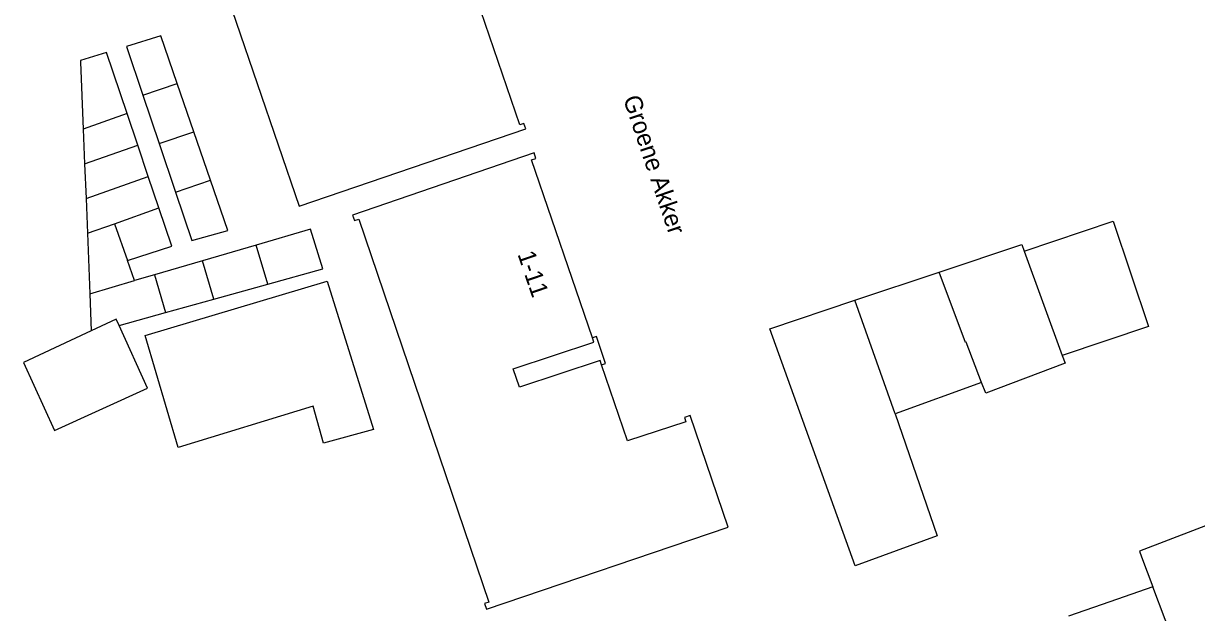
# Model space of a CAD drawing. Extents: x 159377 to 159983, y 382996 to 383595.
# Drawn here: x 159781.2 to 159847.9, y 383370 to 383403.5 of the extents above; entities that cross this region are included whole.
import ezdxf

# ---------------------------------------------------------------- set-up
doc = ezdxf.new("R2010")
doc.units = 0
for name, color, linetype in [('IMGEO_Openbare_ruimte_label', 7, 'Continuous'), ('IMGEO_Pand', 7, 'Continuous'), ('IMGEO_Pand_nummerreeks', 7, 'Continuous'), ('IMGEO_Voetpad_op_trap', 7, 'Continuous')]:
    doc.layers.add(name, color=color, linetype=linetype)

msp = doc.modelspace()

# ---------------------------------------------------------------- linework, layer by layer
at = {"layer": 'IMGEO_Pand'}
for points in [[(159802.443, 383426.11), (159787.292, 383421.008), (159796.842, 383393.077), (159809.724, 383397.481), (159809.618, 383397.783), (159809.378, 383397.699), (159805.931, 383407.814)], [(159789.909, 383400.061), (159788.98, 383402.759), (159787.012, 383402.158), (159787.944, 383399.398)], [(159787.05, 383398.343), (159785.875, 383401.81), (159784.411, 383401.363), (159784.414, 383401.275), (159784.564, 383397.464)], [(159787.944, 383399.398), (159789.909, 383400.061)], [(159790.857, 383397.306), (159789.909, 383400.061)], [(159787.944, 383399.398), (159788.876, 383396.638)], [(159787.05, 383398.343), (159784.564, 383397.464)], [(159787.658, 383396.548), (159787.05, 383398.343)], [(159784.564, 383397.464), (159784.642, 383395.479)], [(159788.876, 383396.638), (159790.857, 383397.306)], [(159791.805, 383394.552), (159790.857, 383397.306)], [(159784.642, 383395.479), (159787.658, 383396.548)], [(159788.261, 383394.77), (159787.658, 383396.548)], [(159788.876, 383396.638), (159789.808, 383393.877)], [(159813.511, 383385.584), (159810.051, 383395.708), (159810.296, 383395.789), (159810.192, 383396.102), (159799.869, 383392.567), (159799.974, 383392.26), (159800.22, 383392.344), (159807.624, 383370.549), (159807.378, 383370.465), (159807.483, 383370.157), (159821.228, 383374.818), (159819.072, 383381.162), (159818.736, 383381.063), (159818.821, 383380.801), (159815.509, 383379.736), (159814.034, 383384.051)], [(159784.642, 383395.479), (159784.719, 383393.516)], [(159784.719, 383393.516), (159788.261, 383394.77)], [(159788.868, 383392.978), (159788.261, 383394.77)], [(159789.808, 383393.877), (159791.805, 383394.552)], [(159789.808, 383393.877), (159790.74, 383391.117), (159792.789, 383391.694), (159791.805, 383394.552)], [(159784.719, 383393.516), (159784.797, 383391.537)], [(159786.33, 383392.08), (159788.868, 383392.978)], [(159787.071, 383389.988), (159789.607, 383390.797), (159788.868, 383392.978)], [(159784.797, 383391.537), (159786.33, 383392.08)], [(159786.33, 383392.08), (159787.071, 383389.988)], [(159795.047, 383388.641), (159798.177, 383389.516), (159797.482, 383391.759), (159794.399, 383390.86)], [(159838.062, 383390.523), (159843.11, 383392.215), (159845.116, 383386.23), (159840.221, 383384.589)], [(159784.797, 383391.537), (159784.932, 383388.099)], [(159794.399, 383390.86), (159791.346, 383389.969)], [(159795.047, 383388.641), (159794.399, 383390.86)], [(159833.221, 383389.329), (159837.923, 383390.905), (159838.062, 383390.523)], [(159838.062, 383390.523), (159840.221, 383384.589)], [(159787.477, 383388.841), (159787.071, 383389.988)], [(159791.346, 383389.969), (159788.605, 383389.17)], [(159791.981, 383387.795), (159791.346, 383389.969)], [(159788.605, 383389.17), (159787.477, 383388.841)], [(159788.605, 383389.17), (159789.231, 383387.026)], [(159828.421, 383387.721), (159833.221, 383389.329)], [(159835.635, 383383.05), (159834.751, 383385.337), (159834.725, 383385.327), (159833.221, 383389.329)], [(159784.932, 383388.099), (159787.477, 383388.841)], [(159798.433, 383388.808), (159801.069, 383380.372), (159798.213, 383379.597), (159797.642, 383381.699), (159789.954, 383379.355), (159788.085, 383385.727), (159798.433, 383388.808)], [(159791.981, 383387.795), (159792.662, 383387.985), (159792.665, 383387.975), (159795.047, 383388.641)], [(159784.932, 383388.099), (159785.015, 383385.982)], [(159789.231, 383387.026), (159791.981, 383387.795)], [(159830.719, 383381.268), (159833.108, 383374.317), (159828.455, 383372.618), (159823.591, 383386.102), (159828.421, 383387.721)], [(159830.719, 383381.268), (159828.421, 383387.721)], [(159786.6, 383386.29), (159789.231, 383387.026)], [(159786.6, 383386.29), (159786.44, 383386.646), (159785.015, 383385.982)], [(159785.015, 383385.982), (159781.163, 383384.188), (159782.932, 383380.31), (159788.208, 383382.717), (159786.6, 383386.29)], [(159814.034, 383384.051), (159813.951, 383384.296), (159809.356, 383382.771), (159809, 383383.814), (159813.594, 383385.339), (159813.511, 383385.584)], [(159840.221, 383384.589), (159840.38, 383384.152), (159835.874, 383382.43), (159835.635, 383383.05)], [(159835.635, 383383.05), (159830.719, 383381.268)], [(159850.332, 383373.15), (159850.322, 383373.18), (159849.63, 383375), (159849.507, 383375.324), (159844.604, 383373.459), (159844.726, 383373.135), (159845.368, 383371.426)], [(159845.368, 383371.426), (159842.919, 383370.575), (159840.573, 383369.76)], [(159849.765, 383359.071), (159846.807, 383367.595), (159846.769, 383367.697), (159845.368, 383371.426)]]:
    msp.add_lwpolyline(points, dxfattribs=at)
at = {"layer": 'IMGEO_Voetpad_op_trap'}
msp.add_lwpolyline([(159814.034, 383384.051), (159814.262, 383384.127), (159813.738, 383385.66), (159813.511, 383385.584)], dxfattribs=at)

# ---------------------------------------------------------------- texts
at = {"layer": 'IMGEO_Openbare_ruimte_label'}
msp.add_text('Groene Akker', height=1, rotation=288.67058, dxfattribs=at).set_placement((159815.242, 383399.192))
at = {"layer": 'IMGEO_Pand_nummerreeks'}
msp.add_text('1-11', height=1, rotation=288.86729, dxfattribs=at).set_placement((159809.242, 383390.345))

doc.saveas('drawing.dxf')
